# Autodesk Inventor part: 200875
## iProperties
Created: 2007-10
Part Number: 200875
Document SubType Name: Modeling
Designer: TH
Density: 7.85 g/cm^3
Mass: 510.334 g
Surface Area: 671.811 cm^2
Volume: 65.0106 cm^3
Material: Steel
Description: RAIL SIDE - RIGHT INNER
Component Category: Lower Component
Author: TH
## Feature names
1. TaggingFeature3
